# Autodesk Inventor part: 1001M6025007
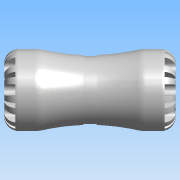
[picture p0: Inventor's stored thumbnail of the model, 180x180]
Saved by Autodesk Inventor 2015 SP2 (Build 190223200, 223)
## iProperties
Created: 2016-12
Part Number: 1001M6025007
Material: PVC-Piping
Description: PLASSON COUPLER METRIC TO IMPERIAL 25X3/4" SERIES 1
Document SubType Name: Modeling
Designer: KIM
Mass: 95.2094 g
Surface Area: 200.83 cm^2
Volume: 68.0067 cm^3
Density: 1.4 g/cm^3
Appearance: Smooth - White
ILogicFactory: False
Author: KIM
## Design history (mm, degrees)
derived "1001M.ipt"
feature "Solid1::1001M.ipt"
tag "TaggingFeature1"
body "Solid1"
other parameters: "d2" = 48, "d11" = 6.3, "d13" = 6.3, "d14" = 0, "d16" = 360 deg, "d18" = 8 deg, "d19" = 0.5, "d20" = 8 deg, "d21" = 0.5, "d23" = 0, "d25" = 360 deg, "d27" = 18.8, "d28" = 7.5, "d29" = 7.5, "d30" = 12.348, "d31" = 0, "d33" = 0, "d37" = 19.6, "d38" = 0.47, "d44" = 25, "d45" = 19.6, "d46" = 39.95, "d47" = 47, "d50" = 360 deg, "d54" = 0.513, "d61" = 31.25, "d64" = 98, "d66" = 1.5875, "d67" = 49, "d70" = 6.3, "d72" = 6.3, "d73" = 0, "d75" = 360 deg, "d77" = 8 deg, "d78" = 8 deg, "d79" = 0.5, "d80" = 0.5, "d82" = 0, "d84" = 360 deg, "d87" = 31.25, "d93" = 19.05, "d_" = 25, "E_" = 47, "H_" = 98, "l_" = 48, "d_1" = 19.05, "d12" = 31.25, "d42" = 47, "d52" = 7.875, "d68" = 47, "d69" = 31.25, "d71" = 7.875
